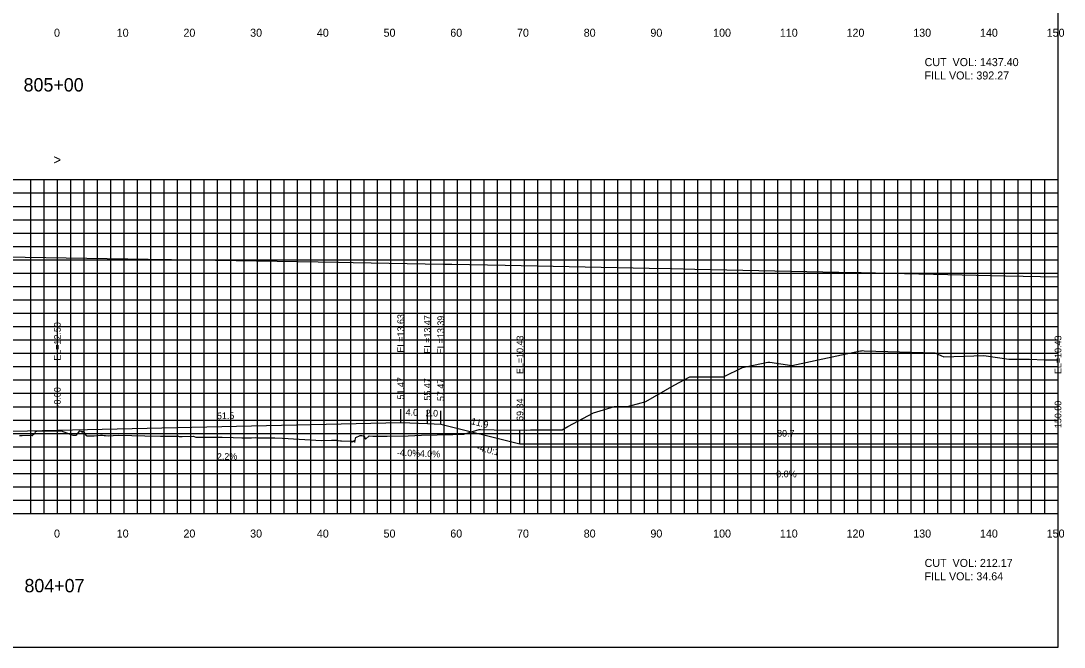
# Model space of a CAD drawing. Extents: x 1797419 to 1809236, y 248759 to 251512.
# Drawn here: x 1803305.5 to 1803461.9, y 250417.3 to 250511 of the extents above; entities that cross this region are included whole.
import ezdxf

# ---------------------------------------------------------------- set-up
doc = ezdxf.new("R2010")
doc.units = 0
for name, color, linetype in [('1', 7, 'Continuous'), ('10', 7, 'Continuous'), ('3', 7, 'Continuous'), ('4', 7, 'Continuous'), ('60', 7, 'Continuous'), ('ANNO-TXT', 7, 'Continuous'), ('CL-CNST', 7, 'Continuous'), ('Level 62', 7, 'Continuous'), ('M-ROADS', 7, 'Continuous')]:
    doc.layers.add(name, color=color, linetype=linetype)

msp = doc.modelspace()

# ---------------------------------------------------------------- linework, layer by layer
for p, q in [((1803362.47, 250450.89), (1803362.47, 250452.89)), ((1803366.47, 250450.73), (1803366.47, 250452.73)), ((1803368.47, 250450.65), (1803368.47, 250452.65)), ((1803311, 250449.76), (1803311, 250451.76)), ((1803380.34, 250447.68), (1803380.34, 250449.68)), ((1803461, 250447.68), (1803461, 250449.68))]:
    msp.add_line(p, q)
msp.add_lwpolyline([(1803161, 250417.26), (1803461, 250417.26), (1803461, 250607.26), (1803161, 250607.26)], close=True)
at = {"layer": '60'}
for p, q in [((1803461, 250437.26), (1803461, 250487.26)), ((1803461.06, 250487.26), (1803461, 250487.26)), ((1803461.06, 250477.26), (1803461, 250477.26)), ((1803461.06, 250467.26), (1803461, 250467.26)), ((1803461.06, 250457.26), (1803461, 250457.26)), ((1803461.06, 250447.26), (1803461, 250447.26)), ((1803161, 250437.26), (1803461, 250437.26)), ((1803311, 250437.2), (1803311, 250437.26)), ((1803321, 250437.2), (1803321, 250437.26)), ((1803331, 250437.2), (1803331, 250437.26)), ((1803341, 250437.2), (1803341, 250437.26)), ((1803351, 250437.2), (1803351, 250437.26)), ((1803361, 250437.2), (1803361, 250437.26)), ((1803371, 250437.2), (1803371, 250437.26)), ((1803381, 250437.2), (1803381, 250437.26)), ((1803391, 250437.2), (1803391, 250437.26)), ((1803401, 250437.2), (1803401, 250437.26)), ((1803411, 250437.2), (1803411, 250437.26)), ((1803421, 250437.2), (1803421, 250437.26)), ((1803431, 250437.2), (1803431, 250437.26)), ((1803441, 250437.2), (1803441, 250437.26)), ((1803451, 250437.2), (1803451, 250437.26)), ((1803461, 250437.2), (1803461, 250437.26)), ((1803461.06, 250437.26), (1803461, 250437.26))]:
    msp.add_line(p, q, dxfattribs=at)
at = {"layer": 'CL-CNST'}
for points in [[(1803303.12, 250475.72), (1803324.59, 250475.37), (1803328.12, 250475.32), (1803331.64, 250475.26), (1803353.12, 250474.89), (1803355.32, 250474.85), (1803368.85, 250474.6), (1803368.85, 250474.6), (1803368.86, 250474.6), (1803370.14, 250474.58), (1803378.12, 250474.43), (1803399.69, 250474.01), (1803403.12, 250473.94), (1803406.54, 250473.87), (1803428.12, 250473.42), (1803431.51, 250473.35), (1803453.12, 250472.88), (1803461, 250472.7)], [(1803244, 250448.18), (1803246, 250448.26), (1803250, 250448.42), (1803311, 250449.76), (1803362.47, 250450.89), (1803366.47, 250450.73), (1803368.47, 250450.65), (1803380.34, 250447.68), (1803461, 250447.68)]]:
    msp.add_lwpolyline(points, dxfattribs=at)
at = {"layer": 'Level 62'}
for p, q in [((1803161, 250487.26), (1803461, 250487.26)), ((1803307, 250437.26), (1803307, 250487.26)), ((1803309, 250437.26), (1803309, 250487.26)), ((1803311, 250437.26), (1803311, 250487.26)), ((1803313, 250437.26), (1803313, 250487.26)), ((1803315, 250437.26), (1803315, 250487.26)), ((1803317, 250437.26), (1803317, 250487.26)), ((1803319, 250437.26), (1803319, 250487.26)), ((1803321, 250437.26), (1803321, 250487.26)), ((1803323, 250437.26), (1803323, 250487.26)), ((1803325, 250437.26), (1803325, 250487.26)), ((1803327, 250437.26), (1803327, 250487.26)), ((1803329, 250437.26), (1803329, 250487.26)), ((1803331, 250437.26), (1803331, 250487.26)), ((1803333, 250437.26), (1803333, 250487.26)), ((1803335, 250437.26), (1803335, 250487.26)), ((1803337, 250437.26), (1803337, 250487.26)), ((1803339, 250437.26), (1803339, 250487.26)), ((1803341, 250437.26), (1803341, 250487.26)), ((1803343, 250437.26), (1803343, 250487.26)), ((1803345, 250437.26), (1803345, 250487.26)), ((1803347, 250437.26), (1803347, 250487.26)), ((1803349, 250437.26), (1803349, 250487.26)), ((1803351, 250437.26), (1803351, 250487.26)), ((1803353, 250437.26), (1803353, 250487.26)), ((1803355, 250437.26), (1803355, 250487.26)), ((1803357, 250437.26), (1803357, 250487.26)), ((1803359, 250437.26), (1803359, 250487.26)), ((1803361, 250437.26), (1803361, 250487.26)), ((1803363, 250437.26), (1803363, 250487.26)), ((1803365, 250437.26), (1803365, 250487.26)), ((1803367, 250437.26), (1803367, 250487.26)), ((1803369, 250437.26), (1803369, 250487.26)), ((1803371, 250437.26), (1803371, 250487.26)), ((1803373, 250437.26), (1803373, 250487.26)), ((1803375, 250437.26), (1803375, 250487.26)), ((1803377, 250437.26), (1803377, 250487.26)), ((1803379, 250437.26), (1803379, 250487.26)), ((1803381, 250437.26), (1803381, 250487.26)), ((1803383, 250437.26), (1803383, 250487.26)), ((1803385, 250437.26), (1803385, 250487.26)), ((1803387, 250437.26), (1803387, 250487.26)), ((1803389, 250437.26), (1803389, 250487.26)), ((1803391, 250437.26), (1803391, 250487.26)), ((1803393, 250437.26), (1803393, 250487.26)), ((1803395, 250437.26), (1803395, 250487.26)), ((1803397, 250437.26), (1803397, 250487.26)), ((1803399, 250437.26), (1803399, 250487.26)), ((1803401, 250437.26), (1803401, 250487.26)), ((1803403, 250437.26), (1803403, 250487.26)), ((1803405, 250437.26), (1803405, 250487.26)), ((1803407, 250437.26), (1803407, 250487.26)), ((1803409, 250437.26), (1803409, 250487.26)), ((1803411, 250437.26), (1803411, 250487.26)), ((1803413, 250437.26), (1803413, 250487.26)), ((1803415, 250437.26), (1803415, 250487.26)), ((1803417, 250437.26), (1803417, 250487.26)), ((1803419, 250437.26), (1803419, 250487.26)), ((1803421, 250437.26), (1803421, 250487.26)), ((1803423, 250437.26), (1803423, 250487.26)), ((1803425, 250437.26), (1803425, 250487.26)), ((1803427, 250437.26), (1803427, 250487.26)), ((1803429, 250437.26), (1803429, 250487.26)), ((1803431, 250437.26), (1803431, 250487.26)), ((1803433, 250437.26), (1803433, 250487.26)), ((1803435, 250437.26), (1803435, 250487.26)), ((1803437, 250437.26), (1803437, 250487.26)), ((1803439, 250437.26), (1803439, 250487.26)), ((1803441, 250437.26), (1803441, 250487.26)), ((1803443, 250437.26), (1803443, 250487.26)), ((1803445, 250437.26), (1803445, 250487.26)), ((1803447, 250437.26), (1803447, 250487.26)), ((1803449, 250437.26), (1803449, 250487.26)), ((1803451, 250437.26), (1803451, 250487.26)), ((1803453, 250437.26), (1803453, 250487.26)), ((1803455, 250437.26), (1803455, 250487.26)), ((1803457, 250437.26), (1803457, 250487.26)), ((1803459, 250437.26), (1803459, 250487.26)), ((1803461, 250437.26), (1803461, 250487.26)), ((1803161, 250485.26), (1803461, 250485.26)), ((1803161, 250483.26), (1803461, 250483.26)), ((1803161, 250481.26), (1803461, 250481.26)), ((1803161, 250479.26), (1803461, 250479.26)), ((1803161, 250477.26), (1803461, 250477.26)), ((1803161, 250475.26), (1803461, 250475.26)), ((1803161, 250473.26), (1803461, 250473.26)), ((1803161, 250471.26), (1803461, 250471.26)), ((1803161, 250469.26), (1803461, 250469.26)), ((1803161, 250467.26), (1803461, 250467.26)), ((1803161, 250465.26), (1803461, 250465.26)), ((1803161, 250463.26), (1803461, 250463.26)), ((1803161, 250461.26), (1803461, 250461.26)), ((1803161, 250459.26), (1803461, 250459.26)), ((1803161, 250457.26), (1803461, 250457.26)), ((1803161, 250455.26), (1803461, 250455.26)), ((1803161, 250453.26), (1803461, 250453.26)), ((1803161, 250451.26), (1803461, 250451.26)), ((1803161, 250449.26), (1803461, 250449.26)), ((1803161, 250447.26), (1803461, 250447.26)), ((1803161, 250445.26), (1803461, 250445.26)), ((1803161, 250443.26), (1803461, 250443.26)), ((1803161, 250441.26), (1803461, 250441.26)), ((1803161, 250439.26), (1803461, 250439.26)), ((1803161, 250437.26), (1803461, 250437.26))]:
    msp.add_line(p, q, dxfattribs=at)
at = {"layer": 'M-ROADS'}
msp.add_lwpolyline([(1803305.32, 250448.94), (1803305.7, 250448.96), (1803306.92, 250448.98), (1803306.95, 250448.99), (1803307, 250448.98), (1803307.02, 250448.98), (1803307.03, 250448.98), (1803307.05, 250448.99), (1803307.06, 250448.99), (1803307.19, 250449), (1803307.22, 250448.92), (1803307.26, 250448.89), (1803307.37, 250449.08), (1803307.65, 250449.24), (1803307.73, 250449.52), (1803307.75, 250449.57), (1803307.84, 250449.59), (1803307.87, 250449.59), (1803307.92, 250449.59), (1803308.53, 250449.62), (1803309.46, 250449.65), (1803311.41, 250449.65), (1803311.58, 250449.64), (1803313.34, 250449.01), (1803313.78, 250448.98), (1803313.8, 250448.92), (1803314.35, 250449.64), (1803314.58, 250449.59), (1803314.76, 250449.45), (1803314.88, 250449.59), (1803314.92, 250449.54), (1803314.94, 250449.51), (1803314.99, 250449.42), (1803315.28, 250448.98), (1803315.3, 250448.98), (1803315.34, 250448.96), (1803315.37, 250448.95), (1803315.39, 250448.95), (1803315.4, 250448.94), (1803315.42, 250448.95), (1803315.43, 250448.91), (1803315.5, 250448.91), (1803315.63, 250448.91), (1803316.2, 250448.88), (1803316.54, 250448.91), (1803317.49, 250449), (1803317.77, 250448.97), (1803318.02, 250448.96), (1803318.2, 250448.94), (1803318.6, 250448.88), (1803319.39, 250448.93), (1803320.22, 250448.99), (1803324.11, 250448.89), (1803326.48, 250448.83), (1803327.26, 250448.84), (1803328.76, 250448.85), (1803329.14, 250448.83), (1803329.26, 250448.82), (1803329.7, 250448.82), (1803331.43, 250448.85), (1803331.49, 250448.8), (1803331.74, 250448.72), (1803332.95, 250448.72), (1803335.72, 250448.68), (1803337.33, 250448.63), (1803338.65, 250448.59), (1803340.11, 250448.62), (1803340.76, 250448.63), (1803340.95, 250448.61), (1803341.18, 250448.59), (1803342.75, 250448.6), (1803343.29, 250448.59), (1803343.6, 250448.6), (1803344.75, 250448.53), (1803350.58, 250448.2), (1803352.09, 250448.24), (1803352.87, 250448.23), (1803353.11, 250448.2), (1803353.42, 250448.14), (1803353.57, 250448.13), (1803354.88, 250448.08), (1803354.98, 250448.06), (1803355.15, 250447.98), (1803355.16, 250447.93), (1803355.16, 250448.16), (1803355.17, 250448.04), (1803355.21, 250448.1), (1803355.23, 250448.02), (1803355.37, 250448.1), (1803355.42, 250448.14), (1803355.52, 250448.22), (1803355.55, 250448.06), (1803355.56, 250448.02), (1803355.57, 250448), (1803355.58, 250447.96), (1803355.63, 250448.24), (1803355.75, 250448.66), (1803356.38, 250448.95), (1803356.44, 250448.93), (1803356.51, 250448.94), (1803356.65, 250448.92), (1803356.84, 250448.9), (1803356.92, 250448.95), (1803357.21, 250448.39), (1803357.74, 250448.87), (1803358.31, 250448.85), (1803360.45, 250448.86), (1803363.61, 250448.9), (1803365.6, 250448.99), (1803370.3, 250449.09), (1803371.94, 250449.16), (1803373.72, 250449.69), (1803374.22, 250449.83), (1803374.41, 250449.83), (1803376.5, 250449.81), (1803381.37, 250449.75), (1803381.93, 250449.77), (1803384.11, 250449.77), (1803384.35, 250449.77), (1803386.3, 250449.8), (1803386.66, 250449.78), (1803387.53, 250450.28), (1803391.36, 250452.33), (1803394.5, 250453.31), (1803395.34, 250453.31), (1803396.46, 250453.31), (1803398.49, 250453.85), (1803399.21, 250454.04), (1803403.46, 250456.49), (1803405.8, 250457.72), (1803406.19, 250457.74), (1803408.17, 250457.74), (1803409.65, 250457.74), (1803410.86, 250457.74), (1803413.69, 250459.14), (1803417.27, 250459.87), (1803417.48, 250459.91), (1803417.78, 250459.94), (1803421.1, 250459.42), (1803427.83, 250460.86), (1803431.4, 250461.62), (1803431.47, 250461.64), (1803431.56, 250461.64), (1803431.76, 250461.65), (1803431.94, 250461.62), (1803442.55, 250461.33), (1803443.89, 250460.73), (1803449.86, 250460.93), (1803453.62, 250460.39), (1803456.71, 250460.37), (1803458.98, 250460.28), (1803461, 250460.28)], dxfattribs=at)

# ---------------------------------------------------------------- texts
msp.add_text('-4.0:1', height=1, rotation=345.9638).set_placement((1803373.8, 250446.74))
at = {"layer": '1'}
for s, p in [('805+00', (1803305.94, 250500.46)), ('804+07', (1803306.07, 250425.46))]:
    msp.add_text(s, height=2, dxfattribs=at).set_placement(p)
at = {"layer": '10'}
for s, p in [('0', (1803310.5, 250508.66)), ('10', (1803319.9, 250508.66)), ('20', (1803329.9, 250508.66)), ('30', (1803339.9, 250508.66)), ('40', (1803349.9, 250508.66)), ('50', (1803359.9, 250508.66)), ('60', (1803369.9, 250508.66)), ('70', (1803379.9, 250508.66)), ('80', (1803389.9, 250508.66)), ('90', (1803399.9, 250508.66)), ('100', (1803409.3, 250508.66)), ('110', (1803419.3, 250508.66)), ('120', (1803429.3, 250508.66)), ('130', (1803439.3, 250508.66)), ('140', (1803449.3, 250508.66)), ('150', (1803459.3, 250508.66)), ('0', (1803310.5, 250433.66)), ('10', (1803319.9, 250433.66)), ('20', (1803329.9, 250433.66)), ('30', (1803339.9, 250433.66)), ('40', (1803349.9, 250433.66)), ('50', (1803359.9, 250433.66)), ('60', (1803369.9, 250433.66)), ('70', (1803379.9, 250433.66)), ('80', (1803389.9, 250433.66)), ('90', (1803399.9, 250433.66)), ('100', (1803409.3, 250433.66)), ('110', (1803419.3, 250433.66)), ('120', (1803429.3, 250433.66)), ('130', (1803439.3, 250433.66)), ('140', (1803449.3, 250433.66)), ('150', (1803459.3, 250433.66))]:
    msp.add_text(s, height=1.2, dxfattribs=at).set_placement(p)
at = {"layer": '3'}
for s, p in [('EL=12.50', (1803311.5, 250460.15)), ('EL=13.63', (1803362.97, 250461.36)), ('EL=13.47', (1803366.97, 250461.2)), ('EL=13.39', (1803368.97, 250461.12)), ('EL=10.43', (1803380.84, 250458.15)), ('EL=10.43', (1803461.5, 250458.15)), ('51.47', (1803362.97, 250454.34)), ('55.47', (1803366.97, 250454.18)), ('57.47', (1803368.97, 250454.1)), ('-0.00', (1803311.5, 250453.13)), ('69.34', (1803380.84, 250451.13)), ('150.00', (1803461.5, 250450.06))]:
    msp.add_text(s, height=1, rotation=90, dxfattribs=at).set_placement(p)
at = {"layer": '4'}
for s, rotation, p in [('51.5', 1.2603, (1803334.93, 250451.38)), ('4.0', 357.7094, (1803363.19, 250451.96)), ('2.0', 357.7094, (1803366.19, 250451.84)), ('11.9', 345.9638, (1803372.95, 250450.66)), ('2.2%', 1.2603, (1803334.93, 250445.28)), ('-4.0%', 357.7094, (1803361.87, 250445.91)), ('-4.0%', 357.7094, (1803364.87, 250445.79))]:
    msp.add_text(s, height=1, rotation=rotation, dxfattribs=at).set_placement(p)
for s, p in [('80.7', (1803418.89, 250448.78)), ('0.0%', (1803418.76, 250442.68))]:
    msp.add_text(s, height=1, dxfattribs=at).set_placement(p)
at = {"layer": '60'}
msp.add_text('>', height=1.5, dxfattribs=at).set_placement((1803310.39, 250489.51))
at = {"layer": 'ANNO-TXT'}
for s, p in [('CUT  VOL: 1437.40', (1803441, 250504.26)), ('FILL VOL: 392.27', (1803441, 250502.26)), ('CUT  VOL: 212.17', (1803441, 250429.26)), ('FILL VOL: 34.64', (1803441, 250427.26))]:
    msp.add_text(s, height=1.2, dxfattribs=at).set_placement(p)

doc.saveas('drawing.dxf')
